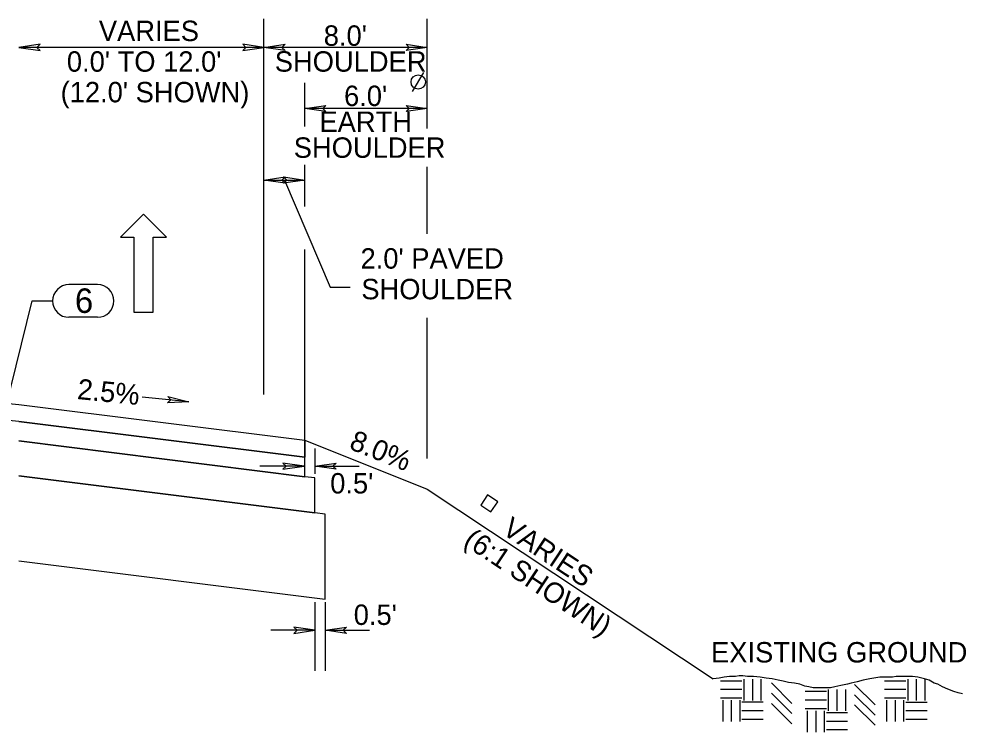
# Model space of a CAD drawing. Extents: x 2003207 to 2014043, y 843846 to 860154.
# Drawn here: x 2013733.39 to 2013779.78, y 844001.9 to 844036.82 of the extents above; entities that cross this region are included whole.
import ezdxf

# ---------------------------------------------------------------- set-up
doc = ezdxf.new("R2010")
doc.units = 0
for name, color, linetype in [('RD_EX_Road_txCode', 7, 'Continuous'), ('RD_QTY_Base_Course', 7, 'Continuous'), ('RD_QTY_ConcPave', 7, 'Continuous'), ('RD_QTY_Intermediate', 7, 'Continuous'), ('RD_QTY_PermVeg', 7, 'Continuous'), ('RD_QTY_Surf_Course', 7, 'Continuous'), ('RD_TX_Misc2', 7, 'Continuous'), ('RD_TX_TypSect', 7, 'Continuous'), ('RD_XS_ExGround', 7, 'Continuous')]:
    doc.layers.add(name, color=color, linetype=linetype)

msp = doc.modelspace()

# ---------------------------------------------------------------- linework, layer by layer
at = {"layer": 'RD_EX_Road_txCode'}
msp.add_lwpolyline([(2013756.014, 844013.012), (2013756.515, 844012.681), (2013756.846, 844013.181), (2013756.346, 844013.513)], close=True, dxfattribs=at)
at = {"layer": 'RD_QTY_Base_Course'}
for p, q in [((2013747.392, 844014.406), (2013733.392, 844016.156)), ((2013747.892, 844012.639), (2013733.392, 844014.451)), ((2013733.392, 844014.451), (2013747.892, 844012.639)), ((2013747.892, 844014.343), (2013747.392, 844014.406)), ((2013747.892, 844012.639), (2013747.892, 844014.343)), ((2013748.392, 844012.576), (2013747.892, 844012.639)), ((2013748.392, 844012.576), (2013747.892, 844012.639)), ((2013748.392, 844008.409), (2013748.392, 844012.576)), ((2013748.392, 844008.409), (2013748.392, 844012.576)), ((2013733.392, 844010.284), (2013748.392, 844008.409)), ((2013733.392, 844010.284), (2013748.392, 844008.409))]:
    msp.add_line(p, q, dxfattribs=at)
at = {"layer": 'RD_QTY_ConcPave'}
for p, q in [((2013733.392, 844014.451), (2013747.892, 844012.639)), ((2013747.892, 844014.343), (2013747.392, 844014.406)), ((2013747.892, 844012.639), (2013747.892, 844014.343))]:
    msp.add_line(p, q, dxfattribs=at)
at = {"layer": 'RD_QTY_Intermediate'}
for p, q in [((2013733.392, 844016.156), (2013747.392, 844014.406)), ((2013733.392, 844016.156), (2013747.392, 844014.406)), ((2013747.392, 844014.406), (2013747.392, 844015.353)), ((2013747.392, 844014.406), (2013747.392, 844015.353))]:
    msp.add_line(p, q, dxfattribs=at)
msp.add_lwpolyline([(2013747.392, 844015.353), (2013733.392, 844017.103), (2013701.892, 844020.253)], dxfattribs=at)
at = {"layer": 'RD_QTY_PermVeg'}
for p, q in [((2013747.392, 844016.186), (2013753.392, 844013.786)), ((2013753.392, 844013.786), (2013767.392, 844004.508))]:
    msp.add_line(p, q, dxfattribs=at)
at = {"layer": 'RD_QTY_Surf_Course'}
for p, q in [((2013733.392, 844017.936), (2013747.392, 844016.186)), ((2013733.392, 844017.103), (2013747.392, 844015.353)), ((2013747.392, 844016.186), (2013747.392, 844015.353))]:
    msp.add_line(p, q, dxfattribs=at)
msp.add_lwpolyline([(2013656.392, 844015.353), (2013656.392, 844016.186), (2013670.392, 844017.936), (2013701.892, 844021.086), (2013733.392, 844017.936), (2013747.392, 844016.186), (2013747.392, 844015.353), (2013733.392, 844017.103), (2013701.892, 844020.253), (2013670.392, 844017.103)], close=True, dxfattribs=at)
at = {"layer": 'RD_TX_Misc2'}
for p, q in [((2013737.243, 844023.811), (2013735.843, 844023.811)), ((2013737.243, 844022.211), (2013735.843, 844022.211))]:
    msp.add_line(p, q, dxfattribs=at)
for centre, start, end in [((2013735.843, 844023.011), 90, 270), ((2013737.243, 844023.011), 270, 90)]:
    msp.add_arc(centre, 0.8, start, end, dxfattribs=at)
at = {"layer": 'RD_TX_TypSect'}
for p, q in [((2013745.392, 844018.436), (2013745.392, 844036.824)), ((2013753.392, 844031.459), (2013753.392, 844036.824)), ((2013745.392, 844035.433), (2013733.392, 844035.433)), ((2013753.392, 844035.433), (2013745.392, 844035.433)), ((2013752.666, 844033.266), (2013753.232, 844034.209)), ((2013747.392, 844031.562), (2013747.392, 844033.691)), ((2013753.392, 844032.433), (2013747.392, 844032.433)), ((2013747.392, 844027.633), (2013747.392, 844029.68)), ((2013753.392, 844026.293), (2013753.392, 844029.577)), ((2013745.392, 844028.933), (2013747.392, 844028.933)), ((2013747.392, 844015.133), (2013747.392, 844025.528)), ((2013753.392, 844015.299), (2013753.392, 844022.18)), ((2013741.712, 844018.073), (2013739.435, 844018.301)), ((2013747.892, 844015.78), (2013747.892, 844014.552)), ((2013747.362, 844014.921), (2013745.195, 844014.921)), ((2013747.892, 844014.921), (2013750.06, 844014.921)), ((2013747.892, 844008.252), (2013747.892, 844004.902)), ((2013748.392, 844008.252), (2013748.392, 844004.902)), ((2013747.892, 844006.88), (2013745.725, 844006.88)), ((2013748.392, 844006.88), (2013750.56, 844006.88))]:
    msp.add_line(p, q, dxfattribs=at)
for points in [[(2013733.392, 844035.433), (2013734.431, 844035.283), (2013734.271, 844035.433), (2013734.431, 844035.583)], [(2013745.392, 844035.433), (2013744.354, 844035.583), (2013744.514, 844035.433), (2013744.354, 844035.283)], [(2013745.392, 844035.433), (2013746.431, 844035.583), (2013746.271, 844035.433), (2013746.431, 844035.283)], [(2013753.392, 844035.433), (2013752.354, 844035.283), (2013752.514, 844035.433), (2013752.354, 844035.583)], [(2013747.392, 844032.433), (2013748.431, 844032.583), (2013748.271, 844032.433), (2013748.431, 844032.283)], [(2013753.392, 844032.433), (2013752.354, 844032.283), (2013752.514, 844032.433), (2013752.354, 844032.583)], [(2013745.392, 844028.933), (2013746.431, 844029.083), (2013746.271, 844028.933), (2013746.431, 844028.783)], [(2013747.392, 844028.933), (2013746.354, 844028.783), (2013746.514, 844028.933), (2013746.354, 844029.083)], [(2013739.014, 844022.461), (2013739.974, 844022.461), (2013739.974, 844026.13), (2013740.625, 844026.13), (2013739.494, 844027.261), (2013738.363, 844026.13), (2013739.014, 844026.13)], [(2013741.712, 844018.073), (2013740.663, 844018.027), (2013740.837, 844018.161), (2013740.693, 844018.326)], [(2013747.362, 844014.921), (2013746.324, 844015.07), (2013746.484, 844014.921), (2013746.324, 844014.771)], [(2013747.892, 844014.921), (2013748.931, 844015.07), (2013748.771, 844014.921), (2013748.931, 844014.771)], [(2013747.892, 844006.88), (2013746.854, 844007.03), (2013747.014, 844006.88), (2013746.854, 844006.73)], [(2013748.392, 844006.88), (2013749.431, 844007.03), (2013749.271, 844006.88), (2013749.431, 844006.73)]]:
    msp.add_lwpolyline(points, close=True, dxfattribs=at)
for points in [[(2013746.392, 844028.933), (2013748.632, 844023.687), (2013749.62, 844023.687)], [(2013732.478, 844016.654), (2013734.034, 844023.011), (2013735.043, 844023.011)]]:
    msp.add_lwpolyline(points, dxfattribs=at)
msp.add_circle((2013752.949, 844033.738), 0.35, dxfattribs=at)
at = {"layer": 'RD_XS_ExGround'}
for p, q in [((2013768.806, 844004.395), (2013767.764, 844004.395)), ((2013768.902, 844004.492), (2013768.902, 844003.451)), ((2013769.319, 844004.492), (2013769.319, 844003.451)), ((2013769.735, 844004.492), (2013769.735, 844003.451)), ((2013776.832, 844004.391), (2013775.791, 844004.391)), ((2013776.929, 844004.487), (2013776.929, 844003.446)), ((2013777.345, 844004.487), (2013777.345, 844003.446)), ((2013777.762, 844004.487), (2013777.762, 844003.446)), ((2013768.806, 844003.979), (2013767.764, 844003.979)), ((2013771.258, 844003.301), (2013770.258, 844004.301)), ((2013773.038, 844003.974), (2013773.038, 844002.932)), ((2013773.455, 844003.974), (2013773.455, 844002.932)), ((2013773.872, 844003.974), (2013773.872, 844002.932)), ((2013775.326, 844003.228), (2013774.326, 844004.228)), ((2013776.832, 844003.974), (2013775.791, 844003.974)), ((2013768.806, 844003.562), (2013767.764, 844003.562)), ((2013767.868, 844003.458), (2013767.868, 844002.416)), ((2013768.285, 844003.458), (2013768.285, 844002.416)), ((2013768.701, 844003.458), (2013768.701, 844002.416)), ((2013771.258, 844002.801), (2013770.258, 844003.801)), ((2013772.942, 844003.877), (2013771.9, 844003.877)), ((2013772.942, 844003.46), (2013771.9, 844003.46)), ((2013775.326, 844002.728), (2013774.326, 844003.728)), ((2013776.832, 844003.557), (2013775.791, 844003.557)), ((2013775.895, 844003.453), (2013775.895, 844002.411)), ((2013776.311, 844003.453), (2013776.311, 844002.411)), ((2013776.728, 844003.453), (2013776.728, 844002.411)), ((2013769.847, 844003.354), (2013768.806, 844003.354)), ((2013771.258, 844002.301), (2013770.258, 844003.301)), ((2013772.942, 844003.043), (2013771.9, 844003.043)), ((2013775.326, 844002.228), (2013774.326, 844003.228)), ((2013777.874, 844003.349), (2013776.832, 844003.349)), ((2013769.847, 844002.937), (2013768.806, 844002.937)), ((2013769.847, 844002.52), (2013768.806, 844002.52)), ((2013772.004, 844002.939), (2013772.004, 844001.898)), ((2013772.421, 844002.939), (2013772.421, 844001.898)), ((2013772.838, 844002.939), (2013772.838, 844001.898)), ((2013773.984, 844002.835), (2013772.942, 844002.835)), ((2013777.874, 844002.932), (2013776.832, 844002.932)), ((2013777.874, 844002.516), (2013776.832, 844002.516)), ((2013773.984, 844002.418), (2013772.942, 844002.418)), ((2013773.984, 844002.002), (2013772.942, 844002.002))]:
    msp.add_line(p, q, dxfattribs=at)
msp.add_lwpolyline([(2013779.618, 844003.775), (2013779.398, 844003.812), (2013779.179, 844003.885), (2013778.886, 844003.995), (2013778.63, 844004.105), (2013778.41, 844004.251), (2013778.227, 844004.288), (2013777.971, 844004.435), (2013777.751, 844004.508), (2013777.422, 844004.581), (2013777.166, 844004.618), (2013776.873, 844004.618), (2013776.543, 844004.618), (2013776.36, 844004.618), (2013776.177, 844004.581), (2013775.958, 844004.581), (2013775.738, 844004.581), (2013775.555, 844004.581), (2013775.262, 844004.544), (2013775.079, 844004.508), (2013774.75, 844004.435), (2013774.457, 844004.361), (2013774.164, 844004.288), (2013773.981, 844004.251), (2013773.652, 844004.178), (2013773.359, 844004.105), (2013773.139, 844004.068), (2013772.956, 844004.068), (2013772.736, 844004.068), (2013772.517, 844004.068), (2013772.297, 844004.068), (2013772.078, 844004.105), (2013771.895, 844004.142), (2013771.638, 844004.251), (2013771.382, 844004.288), (2013771.089, 844004.325), (2013770.833, 844004.398), (2013770.577, 844004.435), (2013770.284, 844004.508), (2013769.991, 844004.544), (2013769.698, 844004.581), (2013769.369, 844004.618), (2013769.076, 844004.618), (2013768.856, 844004.654), (2013768.673, 844004.654), (2013768.49, 844004.618), (2013768.198, 844004.618), (2013767.941, 844004.581), (2013767.685, 844004.544), (2013767.392, 844004.508)], dxfattribs=at)

# ---------------------------------------------------------------- texts
at = {"layer": 'RD_TX_Misc2'}
msp.add_text('6', height=1.2, dxfattribs=at).set_placement((2013736.136, 844022.426))
at = {"layer": 'RD_TX_TypSect'}
for s, p in [('VARIES', (2013737.307, 844035.74)), ("8.0'", (2013748.324, 844035.508)), ("0.0' TO 12.0'", (2013735.74, 844034.24)), ('SHOULDER', (2013745.924, 844034.241)), ("(12.0' SHOWN)", (2013735.433, 844032.74)), ("6.0'", (2013749.317, 844032.558)), ('EARTH', (2013748.113, 844031.291)), ('SHOULDER', (2013746.853, 844030.023)), ("2.0' PAVED", (2013750.125, 844024.594)), ('SHOULDER', (2013750.164, 844023.094)), ("0.5'", (2013748.639, 844013.582)), ("0.5'", (2013749.791, 844007.144)), ('EXISTING GROUND', (2013767.293, 844005.305))]:
    msp.add_text(s, height=1, dxfattribs=at).set_placement(p)
for s, rotation, p in [('2.5%', 354.2894, (2013736.219, 844018.212)), ('8.0%', 338.1986, (2013749.515, 844015.785)), ('VARIES', 326.4658, (2013756.999, 844011.65)), ('(6:1 SHOWN)', 326.4658, (2013755.114, 844011.1))]:
    msp.add_text(s, height=1, rotation=rotation, dxfattribs=at).set_placement(p)

doc.saveas('drawing.dxf')
